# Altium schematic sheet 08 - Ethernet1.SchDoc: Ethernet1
size A3; PageSetup: Record=PageOptions¦CenterHorizontal=True¦CenterVertical=True¦PrintScale=0.70¦XCorrection=1.00¦YCorrection=1.00¦PrintKind=0¦BorderSize=5000000¦LeftOffset=0¦BottomOffset=0¦Orientation=2¦PaperLength=4200¦PaperWidth=2970¦Scale=100¦PaperSource=7¦PrintQuality=600¦MediaType=1¦DitherType=10¦PaperKind=A4¦PrintScaleMode=1; Author: Juan Anzola; SheetNumber: 8; SheetTotal: 17
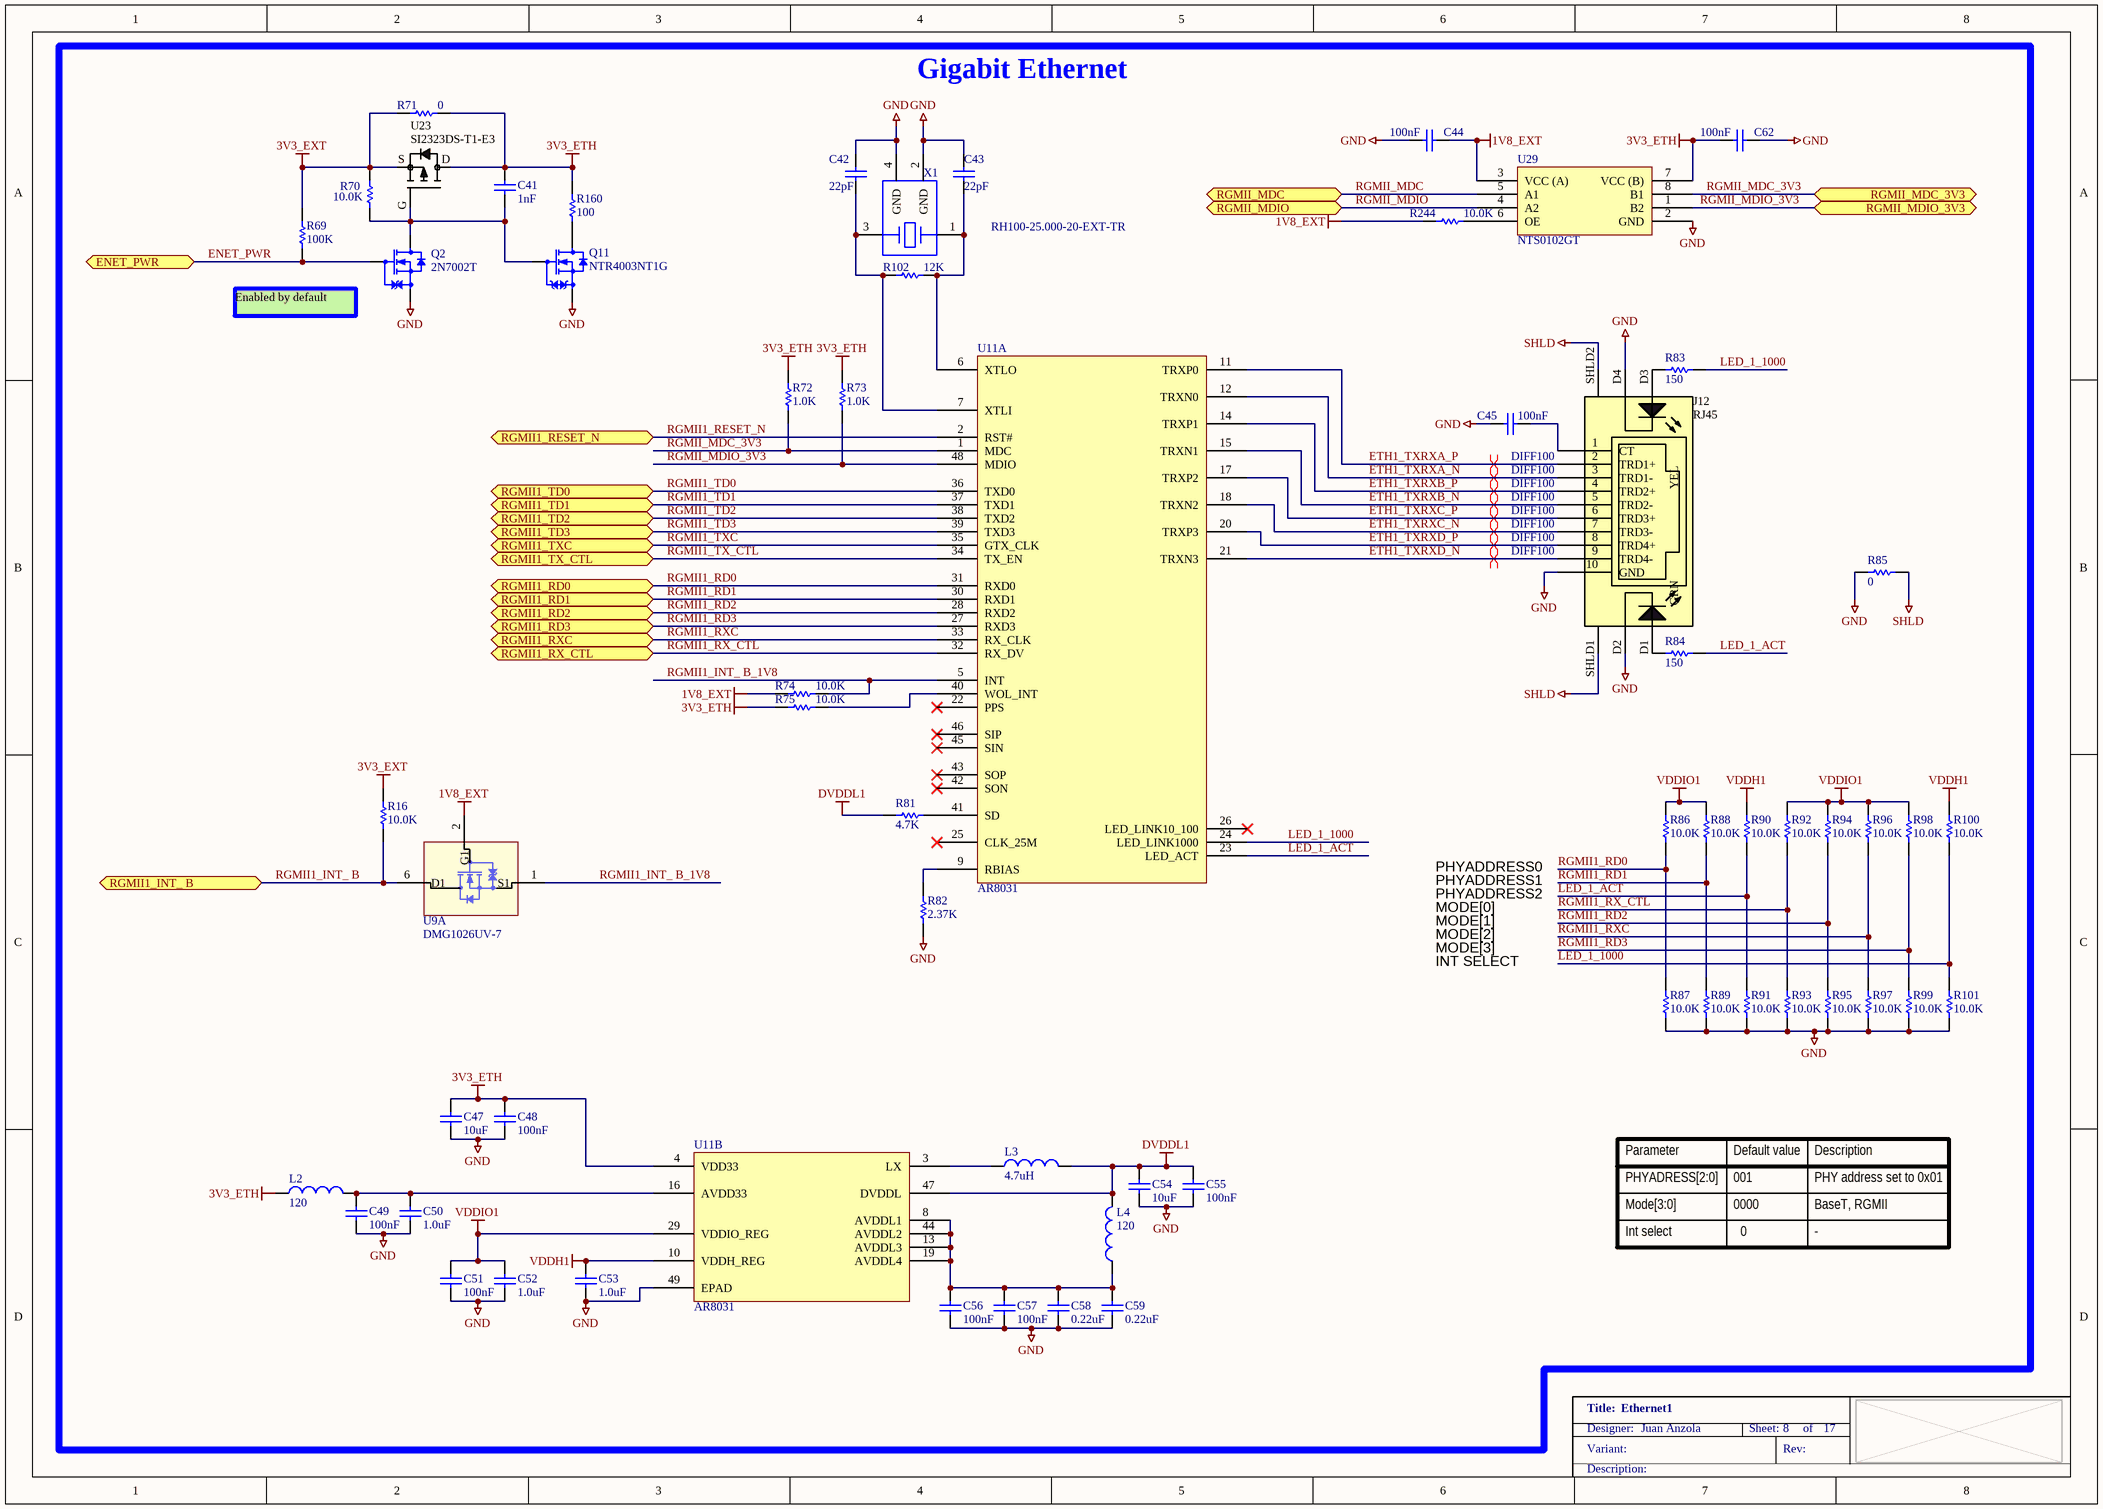
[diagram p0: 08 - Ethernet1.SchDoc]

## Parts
C41  1nF  [CAPC1005X55N]
C42  22pF  [CAPC1005X55N]
C43  22pF  [CAPC1005X55N]
C44  100nF  [CAPC1005X55N]
C45  100nF  [CAPC1005X55N]
C47  10uF  [CAPC1005X55N]
C48  100nF  [CAPC1005X55N]
C49  100nF  [CAPC1005X55N]
C50  1.0uF  [CAPC1005X55N]
C51  100nF  [CAPC1005X55N]
C52  1.0uF  [CAPC1005X55N]
C53  1.0uF  [CAPC1005X55N]
C54  10uF  [CAPC1005X55N]
C55  100nF  [CAPC1005X55N]
C56  100nF  [CAPC1005X55N]
C57  100nF  [CAPC1005X55N]
C58  0.22uF  [CAPC1005X55N]
C59  0.22uF  [CAPC1005X55N]
C62  100nF  [CAPC1005X55N]
J12  RJ45  [XMULTIPLE_XMG-J1B211]
L2  120  [INDC1005X60N]
L3  4.7uH  [INDC2520X100L60N]
L4  120  [INDC1005X60N]
Q2  2N7002T  [SOTFL50P160X80_GSD-3N]
Q11  NTR4003NT1G  [SOT95P240X110_GSD-3N]
R16  10.0K  [RESC1005X40N]
R69  100K  [RESC1005X40N]
R70  10.0K  [RESC1005X40N]
R71  0  [RESC1609X55N]
R72  1.0K  [RESC1005X40N]
R73  1.0K  [RESC1005X40N]
R74  10.0K  [RESC1005X40N]
R75  10.0K  [RESC1005X40N]
R81  4.7K  [RESC1005X40N]
R82  2.37K  [RESC1005X40N]
R83  150  [RESC1005X40N]
R84  150  [RESC1005X40N]
R85  0  [RESC3225X60N]
R86  10.0K  [RESC1005X40N]
R87  10.0K  [RESC1005X40N]
R88  10.0K  [RESC1005X40N]
R89  10.0K  [RESC1005X40N]
R90  10.0K  [RESC1005X40N]
R91  10.0K  [RESC1005X40N]
R92  10.0K  [RESC1005X40N]
R93  10.0K  [RESC1005X40N]
R94  10.0K  [RESC1005X40N]
R95  10.0K  [RESC1005X40N]
R96  10.0K  [RESC1005X40N]
R97  10.0K  [RESC1005X40N]
R98  10.0K  [RESC1005X40N]
R99  10.0K  [RESC1005X40N]
R100  10.0K  [RESC1005X40N]
R101  10.0K  [RESC1005X40N]
R102  12K  [RESC1609X55N]
R160  100  [RESC1005X40N]
R244  10.0K  [RESC1005X40N]
U9  DMG1026UV-7  [SOTFL50P160X60-6N]  (part A of 2)
U11  AR8031  [QFN40P600X600X80-49T380N]  (parts A,B of 2)
U23  SI2323DS-T1-E3  [SOT95P240X110_GSD-3N]
U29  NTS0102GT  [PSON50P195X100X50-8N]
X1  RH100-25.000-20-EXT-TR  [OSC210P320X250X90-4N]

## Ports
ENET_PWR (bidir), RGMII1_INT_ B (bidir), RGMII1_RD0 (bidir), RGMII1_RD1 (bidir), RGMII1_RD2 (bidir), RGMII1_RD3 (bidir), RGMII1_RESET_N (bidir), RGMII1_RX_CTL (bidir), RGMII1_RXC (bidir), RGMII1_TD0 (bidir), RGMII1_TD1 (bidir), RGMII1_TD2 (bidir), RGMII1_TD3 (bidir), RGMII1_TX_CTL (bidir), RGMII1_TXC (bidir), RGMII_MDC (bidir), RGMII_MDC_3V3 (bidir), RGMII_MDIO (bidir), RGMII_MDIO_3V3 (bidir)

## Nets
1V8_EXT: C44.2 R74.2 R244.1 U9.2(G1) U29.3(VCC_(A))
3V3_ETH: C41.2 C47.2 C48.2 C62.2 L2.1 R71.2 R72.2 R73.2 R75.2 R160.2 U11.4(VDD33) U23.D U29.7(VCC_(B))
3V3_EXT: R16.1 R69.1 R70.1 R71.1 U23.S
DVDDL1: C54.2 C55.2 L3.2 L4.2 R81.1 U11.47(DVDDL)
GND: C42.1 C43.1 C44.1 C45.1 C47.1 C48.1 C49.1 C50.1 C51.1 C52.1 C53.1 C54.1 C55.1 C56.1 C57.1 C58.1 C59.1 C62.1 J12.10(GND) J12.D2 J12.D4 Q2.S Q11.S R82.1 R85.1 R87.1 R89.1 R91.1 R93.1 R95.1 R97.1 R99.1 R101.1 U11.49(EPAD) U29.2(GND) X1.2(GND) X1.4(GND)
SHLD: J12.SHLD1(SHLD) J12.SHLD2(SHLD) R85.2
VDDH1: C53.2 R90.2 R100.2 U11.10(VDDH_REG)
VDDIO1: C51.2 C52.2 R86.2 R88.2 R92.2 R94.2 R96.2 R98.2 U11.29(VDDIO_REG)
ENET_PWR: Q2.G R69.2 ; port ENET_PWR
ETH1_TXRXA_N: J12.3(TRD1-) U11.12(TRXN0)
ETH1_TXRXA_P: J12.2(TRD1+) U11.11(TRXP0)
ETH1_TXRXB_N: J12.5(TRD2-) U11.15(TRXN1)
ETH1_TXRXB_P: J12.4(TRD2+) U11.14(TRXP1)
ETH1_TXRXC_N: J12.7(TRD3-) U11.18(TRXN2)
ETH1_TXRXC_P: J12.6(TRD3+) U11.17(TRXP2)
ETH1_TXRXD_N: J12.9(TRD4-) U11.21(TRXN3)
ETH1_TXRXD_P: J12.8(TRD4+) U11.20(TRXP3)
LED_1_1000: R83.2 R100.1 R101.2 U11.24(LED_LINK1000)
LED_1_ACT: R84.2 R90.1 R91.2 U11.23(LED_ACT)
RGMII1_INT_ B: R16.2 U9.6(D1) ; port RGMII1_INT_ B
RGMII1_INT_ B_1V8: R74.1 U9.1(S1) U11.5(INT)
RGMII1_RD0: R86.1 R87.2 U11.31(RXD0) ; port RGMII1_RD0
RGMII1_RD1: R88.1 R89.2 U11.30(RXD1) ; port RGMII1_RD1
RGMII1_RD2: R94.1 R95.2 U11.28(RXD2) ; port RGMII1_RD2
RGMII1_RD3: R98.1 R99.2 U11.27(RXD3) ; port RGMII1_RD3
RGMII1_RESET_N: U11.2(RST#) ; port RGMII1_RESET_N
RGMII1_RX_CTL: R92.1 R93.2 U11.32(RX_DV) ; port RGMII1_RX_CTL
RGMII1_RXC: R96.1 R97.2 U11.33(RX_CLK) ; port RGMII1_RXC
RGMII1_TD0: U11.36(TXD0) ; port RGMII1_TD0
RGMII1_TD1: U11.37(TXD1) ; port RGMII1_TD1
RGMII1_TD2: U11.38(TXD2) ; port RGMII1_TD2
RGMII1_TD3: U11.39(TXD3) ; port RGMII1_TD3
RGMII1_TX_CTL: U11.34(TX_EN) ; port RGMII1_TX_CTL
RGMII1_TXC: U11.35(GTX_CLK) ; port RGMII1_TXC
RGMII_MDC: U29.5(A1) ; port RGMII_MDC
RGMII_MDC_3V3: R72.1 U11.1(MDC) U29.8(B1) ; port RGMII_MDC_3V3
RGMII_MDIO: U29.4(A2) ; port RGMII_MDIO
RGMII_MDIO_3V3: R73.1 U11.48(MDIO) U29.1(B2) ; port RGMII_MDIO_3V3
NetC41_1: C41.1 Q2.D Q11.G R70.2 U23.G
NetC42_2: C42.2 R102.1 U11.7(XTLI) X1.3
NetC43_2: C43.2 R102.2 U11.6(XTLO) X1.1
NetC45_2: C45.2 J12.1(CT)
NetC49_2: C49.2 C50.2 L2.2 U11.16(AVDD33)
NetC56_2: C56.2 C57.2 C58.2 C59.2 L4.1 U11.8(AVDDL1) U11.13(AVDDL3) U11.19(AVDDL4) U11.44(AVDDL2)
NetJ12_D1: J12.D1 R84.1
NetJ12_D3: J12.D3 R83.1
NetL3_1: L3.1 U11.3(LX)
NetQ11_D: Q11.D R160.1
NetR75_1: R75.1 U11.40(WOL_INT)
NetR81_2: R81.2 U11.41(SD)
NetR82_2: R82.2 U11.9(RBIAS)
NetR244_2: R244.2 U29.6(OE)

Not connected (* = marked no-connect by the designer): U11 22(PPS)* 25(CLK_25M)* 26(LED_LINK10_100)* 42(SON)* 43(SOP)* 45(SIN)* 46(SIP)*

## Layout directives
differential pair; net class DIFF100: ETH1_TXRXA_N, ETH1_TXRXA_P, ETH1_TXRXB_N, ETH1_TXRXB_P, ETH1_TXRXC_N, ETH1_TXRXC_P, ETH1_TXRXD_N, ETH1_TXRXD_P

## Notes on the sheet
- Gigabit Ethernet
- Enabled by default
- PHYADDRESS0
- PHYADDRESS1
- PHYADDRESS2
- MODE[0]
- MODE[1]
- MODE[2]
- MODE[3]
- INT SELECT
- Parameter
- PHYADRESS[2:0]
- Default value
- 001
- Description
- PHY address set to 0x01
- Mode[3:0]
- Int select
- 0000
- 0
- BaseT, RGMII
- -

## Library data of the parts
C41 = 1000067: CAP CER 1000PF 50V 10% X7R 0402; Part_Type: Capacitor; Manufacturer: Murata; Manufacturer_Part_Number: GRM155R71H102KA01D; Digi_PN: 14050737; Component_Life_Cycle_State: Proven; Area: 0,95; Project: Adjustable Foundation
C42 C43 = 1001166: CAP CER 22PF 50V 5% NP0 0402; Part_Type: Capacitor; Manufacturer: Murata; Manufacturer_Part_Number: GRM1555C1H220JA01D; Note: 14050749 = Digi No. for GE WDNU; Digi_PN: 14050367; Component_Life_Cycle_State: Reviewed; Area: 0,95; Project: CCWMX6_SBC board; Temp_Coef: C0G, NP0
C44 C62 = 1000006: CAP 100nF 16V 10% X7R 0402; Part_Type: Capacitor; Manufacturer: Murata; Manufacturer_Part_Number: GRM155R71C104KA88D; Component_Life_Cycle_State: CAD Reviewed; Area: 0.95; Project: KITT; Tolerance: 10; Digi_PN: 14050552
C45 C48 C49 C51 C56 C57 = 1000006: CAP 100nF 16V 10% X7R 0402; Part_Type: Capacitor; Manufacturer: Murata; Manufacturer_Part_Number: GRM155R71C104KA88D; Digi_PN: 14050552; Component_Life_Cycle_State: CAD Reviewed; Area: 0,95; Project: KITT; Tolerance: 10
C47 C54 = 1001168: CAP CER 10UF 10V 20% X5R 0402; Part_Type: Capacitor; Manufacturer: Samsung; Manufacturer_Part_Number: CL05A106MP5NUNC; Digi_PN: 14050689; Component_Life_Cycle_State: Reviewed; Area: 0,95; Project: CCWMX6_SBC board
C50 C52 C53 = 1001167: CAP CER 1UF 10V 10% X5R 0402; Part_Type: Capacitor; Manufacturer: Murata; Manufacturer_Part_Number: GRM155R61A105KE15D; Digi_PN: 14050399; Component_Life_Cycle_State: Reviewed; Area: 0.95; Project: CCWMX6_SBC board
C55 = 1000006: CAP 100nF 16V 10% X7R 0402; Part_Type: Capacitor; Manufacturer: Murata; Manufacturer_Part_Number: GRM155R71C104KA88D; Digi_PN: 14050552; Component_Life_Cycle_State: CAD Reviewed; Area: 0.95; Project: KITT; Tolerance: 10
C58 C59 = 1001883: CAP CER 0.22UF 6.3V X7R 0402; Part_Type: Capacitor; Manufacturer: Taiyo Yuden; Manufacturer_Part_Number: JMK105B7224KV-F; Digi_PN: 14000067; Component_Life_Cycle_State: Reviewed; Area: 2.2; Project: Powerley Energy Bridge; Tolerance: 10%
J12 = 1002612: CONN MAGJACK 1PORT 1000 BASE-T IND; Part_Type: Connector; Manufacturer: XMultiple; Manufacturer_Part_Number: XMG-J1B2211NPA-1-DIG; Digi_PN: 18000772; Component_Life_Cycle_State: Created; Area: 339.5; Project: DIGI CC8X SOM
L2 L4 = 1001175: FERRITE BEAD 120 OHM .35A 0402; Part_Type: Filter; Manufacturer: Wurth Electronics Inc; Manufacturer_Part_Number: 7427927112; Digi_PN: 21000128; Component_Life_Cycle_State: Reviewed; Area: 1,12; Project: CCWMX6_SBC board
L3 = 1002610: FIXED IND 4.7UH 1.1A 110 MOHM; Manufacturer: Samsung; Manufacturer_Part_Number: CIG22L4R7MNE; Digi_PN: 21000590; Component_Life_Cycle_State: Created; Area: 5; Project: DIGI CC8X SOM; Tolerance: 20%
Q2 = 1000715: MOSFET N-CH 60V 115MA SOT-523F; Part_Type: Transistor; Manufacturer: Fairchild Semiconductor; Digi_PN: 17050797; Component_Life_Cycle_State: CAD Reviewed; Area: 3.06; Project: SmartMeter2; Note: 17050841 = Digi No. for GE WDNU
Q11 = 1000306: MOSFET N-CH 30V 500MA SOT-23; Part_Type: Transistor; Manufacturer: On Semiconductor; Digi_PN: 17050809; Component_Life_Cycle_State: Proven; Area: 10,92; Project: Adjustable Foundation
R16 R74 R75 R86-R101 = 1000537: RES 10.0K OHM 1/10W 1% 0402 SMD; Part_Type: Resistor; Manufacturer: Panasonic - ECG; Manufacturer_Part_Number: ERJ-2RKF1002X; Digi_PN: 13051084; Component_Life_Cycle_State: CAD Reviewed; Area: 0,95; Project: KITT; Power_WV_SRF: 100
R69 = 1000480: RES 100K OHM 1/10W 1% 0402 SMD; Part_Type: Resistor; Manufacturer: Panasonic - ECG; Manufacturer_Part_Number: ERJ-2RKF1003X; Digi_PN: 13051063; Component_Life_Cycle_State: CAD Reviewed; Area: 0.95; Project: KITT; Power_WV_SRF: 100
R70 R244 = 1000537: RES 10.0K OHM 1/10W 1% 0402 SMD; Part_Type: Resistor; Manufacturer: Panasonic - ECG; Manufacturer_Part_Number: ERJ-2RKF1002X; Component_Life_Cycle_State: CAD Reviewed; Area: 0.95; Project: KITT; Power_WV_SRF: 100; Digi_PN: 13051084
R71 = 1000208: RES 0.0 OHM 1/10W 0603; Part_Type: Resistor; Manufacturer: Panasonic - ECG; Manufacturer_Part_Number: ERJ-3GEY0R00V; Note: 13051103 = Digi No. for GE WDNU; Digi_PN: 13050568; Component_Life_Cycle_State: Reviewed; Area: 2.5; Project: Adjustable Foundation; Voltage: 75V
R72 R73 = 1000079: RES 1.00K OHM 1/10W 1% 0402 SMD; Part_Type: Resistor; Manufacturer: Panasonic - ECG; Manufacturer_Part_Number: ERJ-2RKF1001X; Digi_PN: 13051085; Component_Life_Cycle_State: Proven; Area: 0,95; Project: Adjustable Foundation; Power_WV_SRF: 10
R81 = 1000038: RES 4.7K OHM 1/10W 5% 0402 SMD; Part_Type: Resistor; Manufacturer: Panasonic - ECG; Manufacturer_Part_Number: ERJ-2GEJ472X; Digi_PN: 13050549; Component_Life_Cycle_State: Proven; Area: 0,95; Project: Adjustable Foundation; Power_WV_SRF: 100; Tolerance: 5
R82 = 1000469: RES 2.37K OHM 1/10W 1% 0402 SMD; Part_Type: Resistor; Manufacturer: Panasonic - ECG; Manufacturer_Part_Number: ERJ-2RKF2371X; Component_Life_Cycle_State: Reviewed; Area: 0.95; Project: SDR Prototype RF Board; Power_WV_SRF: 100; Digi_PN: 13000089
R83 R84 = 1000465: RES 150 OHM 1/10W 1% 0402 SMD; Part_Type: Resistor; Manufacturer: Panasonic - ECG; Manufacturer_Part_Number: ERJ-2RKF1500X; Digi_PN: 13050557; Component_Life_Cycle_State: CAD Reviewed; Area: 0,95; Project: KITT; Power_WV_SRF: 100
R85 = 1000229: RES 0.0 OHM 1/2W 1210 SMD; Part_Type: Resistor; Manufacturer: Vishay Dale; Manufacturer_Part_Number: CRCW12100000Z0EA; Digi_PN: 13050962; Component_Life_Cycle_State: Proven; Area: 11,07; Project: Adjustable Foundation
R102 = 1001200: RES 12.0K OHM 1/10W 1% 0603 SMD; Part_Type: Resistor; Manufacturer: Yageo; Manufacturer_Part_Number: RC0603FR-0712KL; Digi_PN: 13050531; Component_Life_Cycle_State: Reviewed; Area: 2,5; Project: LuCoV2; Power_WV_SRF: 100; Tolerance: 1
R160 = 1000467: RES 100 OHM 1/10W 1% 0402 SMD; Part_Type: Resistor; Manufacturer: Panasonic - ECG; Manufacturer_Part_Number: ERJ-2RKF1000X; Digi_PN: 13051087; Component_Life_Cycle_State: CAD Reviewed; Area: 0,95; Project: KITT
U9 = 1001009: MOSFET DL N-CH 60V 410MA SOT-563; Part_Type: Transistor; Manufacturer: Diodes, Inc.; Digi_PN: 17050796; Component_Life_Cycle_State: Reviewed; Area: 2,89; Project: ConnectCore i.MX6 module
U11 = 1002583: IC TRANSCEIVER ETHERNET 48-QFN; Manufacturer: Qualcomm Atheros, Inc.; Digi_PN: 16000123; Component_Life_Cycle_State: Reviewed; Area: 52.56; Project: DIGI CC8X SOM
U23 = 1001163: MOSFET P-CH 20V 3.7A SOT23-3; Part_Type: IC; Manufacturer: Vishay Siliconix; Digi_PN: 17050358; Component_Life_Cycle_State: Reviewed; Area: 10.92; Project: CCWMX6_SBC board
U29 = 1002597: IC TRANSLATING TXRX 8XSON; Manufacturer: NXP Semiconductors; Manufacturer_Part_Number: NTS0102GT,115; Digi_PN: 16000138; Component_Life_Cycle_State: Created; Area: 3,9; Project: DIGI CC8X SOM
X1 = 1001497: SMCRY,25MHZ 50PPM 20PF RH100 EXT; Part_Type: Crystals-Oscillators; Manufacturer: Raltron; Digi_PN: 20000285; Component_Life_Cycle_State: Reviewed; Area: 3,2; Project: CCWMX6_SBC board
